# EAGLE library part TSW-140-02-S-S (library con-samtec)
THROUGH-HOLE .025" SQ POST HEADER Source: Samtec TSW.pdf
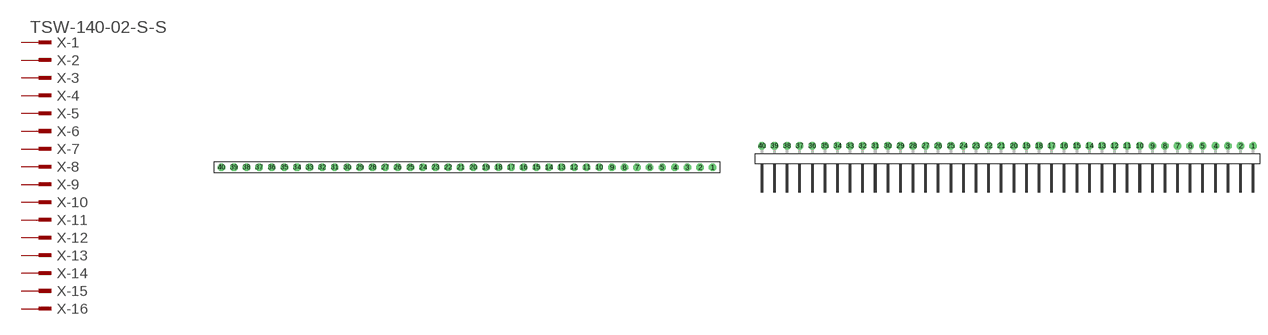
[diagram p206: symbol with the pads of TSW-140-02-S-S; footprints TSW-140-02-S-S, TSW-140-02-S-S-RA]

Designator prefix X; gates -1=MPINV -2=MPIN -3=MPIN -4=MPIN -5=MPIN -6=MPIN -7=MPIN -8=MPIN -9=MPIN -10=MPIN -11=MPIN -12=MPIN -13=MPIN -14=MPIN -15=MPIN -16=MPIN -17=MPIN -18=MPIN -19=MPIN -20=MPIN -21=MPIN -22=MPIN -23=MPIN -24=MPIN -25=MPIN -26=MPIN -27=MPIN -28=MPIN -29=MPIN -30=MPIN -31=MPIN -32=MPIN -33=MPIN -34=MPIN -35=MPIN -36=MPIN -37=MPIN -38=MPIN -39=MPIN -40=MPIN

## TSW-140-02-S-S (OC_FARNELL: unknown; OC_NEWARK: unknown)  [TSW-140-02-S-S]
1  -1:1  pas
2  -2:1  pas
3  -3:1  pas
4  -4:1  pas
5  -5:1  pas
6  -6:1  pas
7  -7:1  pas
8  -8:1  pas
9  -9:1  pas
10  -10:1  pas
11  -11:1  pas
12  -12:1  pas
13  -13:1  pas
14  -14:1  pas
15  -15:1  pas
16  -16:1  pas
17  -17:1  pas
18  -18:1  pas
19  -19:1  pas
20  -20:1  pas
21  -21:1  pas
22  -22:1  pas
23  -23:1  pas
24  -24:1  pas
25  -25:1  pas
26  -26:1  pas
27  -27:1  pas
28  -28:1  pas
29  -29:1  pas
30  -30:1  pas
31  -31:1  pas
32  -32:1  pas
33  -33:1  pas
34  -34:1  pas
35  -35:1  pas
36  -36:1  pas
37  -37:1  pas
38  -38:1  pas
39  -39:1  pas
40  -40:1  pas

## TSW-140-02-S-S-RA (OC_FARNELL: unknown; OC_NEWARK: unknown)  [TSW-140-02-S-S-RA]
Pads as for TSW-140-02-S-S

## Footprint TSW-140-02-S-S (pad centres in mm)
THROUGH-HOLE .025" SQ POST HEADER Source: Samtec TSW.pdf
drill 1 pad 1.5 octagon: 1 49.53,0; 2 46.99,0; 3 44.45,0; 4 41.91,0; 5 39.37,0; 6 36.83,0; 7 34.29,0; 8 31.75,0; 9 29.21,0; 10 26.67,0; 11 24.13,0; 12 21.59,0; 13 19.05,0; 14 16.51,0; 15 13.97,0; 16 11.43,0; 17 8.89,0; 18 6.35,0; 19 3.81,0; 20 1.27,0; 21 -1.27,0; 22 -3.81,0; 23 -6.35,0; 24 -8.89,0; 25 -11.43,0; 26 -13.97,0; 27 -16.51,0; 28 -19.05,0; 29 -21.59,0; 30 -24.13,0; 31 -26.67,0; 32 -29.21,0; 33 -31.75,0; 34 -34.29,0; 35 -36.83,0; 36 -39.37,0; 37 -41.91,0; 38 -44.45,0; 39 -46.99,0; 40 -49.53,0

## Footprint TSW-140-02-S-S-RA (pad centres in mm)
THROUGH-HOLE .025" SQ POST HEADER Source: Samtec TSW.pdf
drill 1 pad 1.5 octagon: 1 49.53,1.524; 2 46.99,1.524; 3 44.45,1.524; 4 41.91,1.524; 5 39.37,1.524; 6 36.83,1.524; 7 34.29,1.524; 8 31.75,1.524; 9 29.21,1.524; 10 26.67,1.524; 11 24.13,1.524; 12 21.59,1.524; 13 19.05,1.524; 14 16.51,1.524; 15 13.97,1.524; 16 11.43,1.524; 17 8.89,1.524; 18 6.35,1.524; 19 3.81,1.524; 20 1.27,1.524; 21 -1.27,1.524; 22 -3.81,1.524; 23 -6.35,1.524; 24 -8.89,1.524; 25 -11.43,1.524; 26 -13.97,1.524; 27 -16.51,1.524; 28 -19.05,1.524; 29 -21.59,1.524; 30 -24.13,1.524; 31 -26.67,1.524; 32 -29.21,1.524; 33 -31.75,1.524; 34 -34.29,1.524; 35 -36.83,1.524; 36 -39.37,1.524; 37 -41.91,1.524; 38 -44.45,1.524; 39 -46.99,1.524; 40 -49.53,1.524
